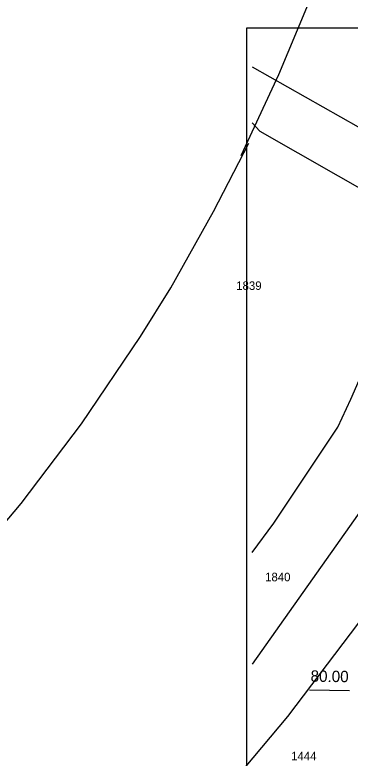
# Model space of a CAD drawing. Extents: x -583721 to -583071, y -1166145 to -1165065.
# Drawn here: x -583557.8 to -583498.8, y -1165295.2 to -1165164.5 of the extents above; entities that cross this region are included whole.
import ezdxf

# ---------------------------------------------------------------- set-up
doc = ezdxf.new("R2010")
doc.units = 0
for name, color, linetype in [('01_DOPRAVA', 7, 'Continuous'), ('56', 7, 'Continuous'), ('Parcelní čísla', 7, 'Continuous'), ('Popis PP', 7, 'Continuous'), ('TISK', 7, 'Continuous'), ('Trojúhelniky', 7, 'Continuous')]:
    doc.layers.add(name, color=color, linetype=linetype)

msp = doc.modelspace()

# ---------------------------------------------------------------- linework, layer by layer
at = {"layer": '01_DOPRAVA'}
for points in [[(-583516.01, -1165173.65), (-583491.16, -1165187.69), (-583480.63, -1165192.3)], [(-583516.01, -1165183.49), (-583514.65, -1165184.96), (-583494.23, -1165196.62), (-583484.79, -1165200.39)], [(-583516.01, -1165259.05), (-583512.23, -1165253.9), (-583500.95, -1165237.01), (-583498.68, -1165232.05), (-583484.79, -1165200.39)], [(-583472.25, -1165207.93), (-583489.98, -1165241.85), (-583516.01, -1165278.67)]]:
    msp.add_lwpolyline(points, dxfattribs=at)
at = {"layer": '56'}
msp.add_lwpolyline([(-583516.97, -1166111.82), (-583516.97, -1165166.82), (-583071.47, -1165166.82), (-583071.47, -1166111.82)], close=True, dxfattribs=at)
at = {"layer": 'Popis PP'}
for points in [[(-583517.94, -1165189.26), (-583511.34, -1165175.01), (-583506.13, -1165162.52), (-583502.47, -1165152.79), (-583498.94, -1165142.58), (-583492.04, -1165120.2), (-583484.52, -1165093.42), (-583478.02, -1165069.74), (-583476.71, -1165064.97)], [(-583720.6, -1165362.96), (-583701.09, -1165355.73), (-583690.3, -1165351.27), (-583674.74, -1165344.25), (-583657.63, -1165335.47), (-583641.46, -1165325.95), (-583627.37, -1165316.61), (-583619.58, -1165311), (-583605.73, -1165300.17), (-583595.62, -1165291.53), (-583588.25, -1165284.77), (-583576.4, -1165272.97), (-583565.67, -1165261.11), (-583556.66, -1165250.39), (-583546.02, -1165236.39), (-583535.66, -1165221.08), (-583530.35, -1165212.48), (-583522.8, -1165199.08), (-583516.6, -1165187.07)], [(-583699.75, -1165419.22), (-583679.21, -1165411.61), (-583666.5, -1165406.36), (-583648.68, -1165398.32), (-583628.68, -1165388.05), (-583609.64, -1165376.84), (-583593.26, -1165365.98), (-583583.56, -1165359), (-583567.75, -1165346.63), (-583555.85, -1165336.47), (-583546.78, -1165328.15), (-583532.96, -1165314.38), (-583520.45, -1165300.56), (-583509.78, -1165287.87), (-583497.25, -1165271.38), (-583485.27, -1165253.68), (-583478.66, -1165242.98), (-583469.98, -1165227.56), (-583463.28, -1165214.57)]]:
    msp.add_lwpolyline(points, dxfattribs=at)
at = {"layer": 'Trojúhelniky'}
msp.add_line((-583498.93, -1165283.35), (-583505.92, -1165283.24), dxfattribs=at)

# ---------------------------------------------------------------- texts
at = {"layer": 'Parcelní čísla'}
for s, p in [('1839', (-583518.83, -1165212.87)), ('1840', (-583513.75, -1165264.09)), ('1444', (-583509.17, -1165295.57))]:
    msp.add_text(s, height=1.5, dxfattribs=at).set_placement(p)
at = {"layer": 'TISK'}
msp.add_text('80.00', height=2, rotation=359.1166, dxfattribs=at).set_placement((-583505.76, -1165281.74))

doc.saveas('drawing.dxf')
